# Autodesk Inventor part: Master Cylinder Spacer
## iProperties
Shininess: 77.0
Angle Display Precision: 2
Document Length Units: 11269
Document Angle Units: 11279
Document Time Units: 11290
Document Mass Units: 11283
Document Length Units Precision: 3
Document Angle Units Precision: 2
Compacted: True
Created: 2001-09
Part Number: Master Cylinder Spacer
Document SubType Name: Modeling
Designer: Martin Budgell
Density: 0.0
Volumn: 0.0
Area: 0.0
PropertySet Name: Model Information
Control State: 0
Master: False
Checked Out: False
Author: Martin Budgell
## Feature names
1. Extrusion1
2. Chamfer1
